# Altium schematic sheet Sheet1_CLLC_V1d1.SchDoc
size A3
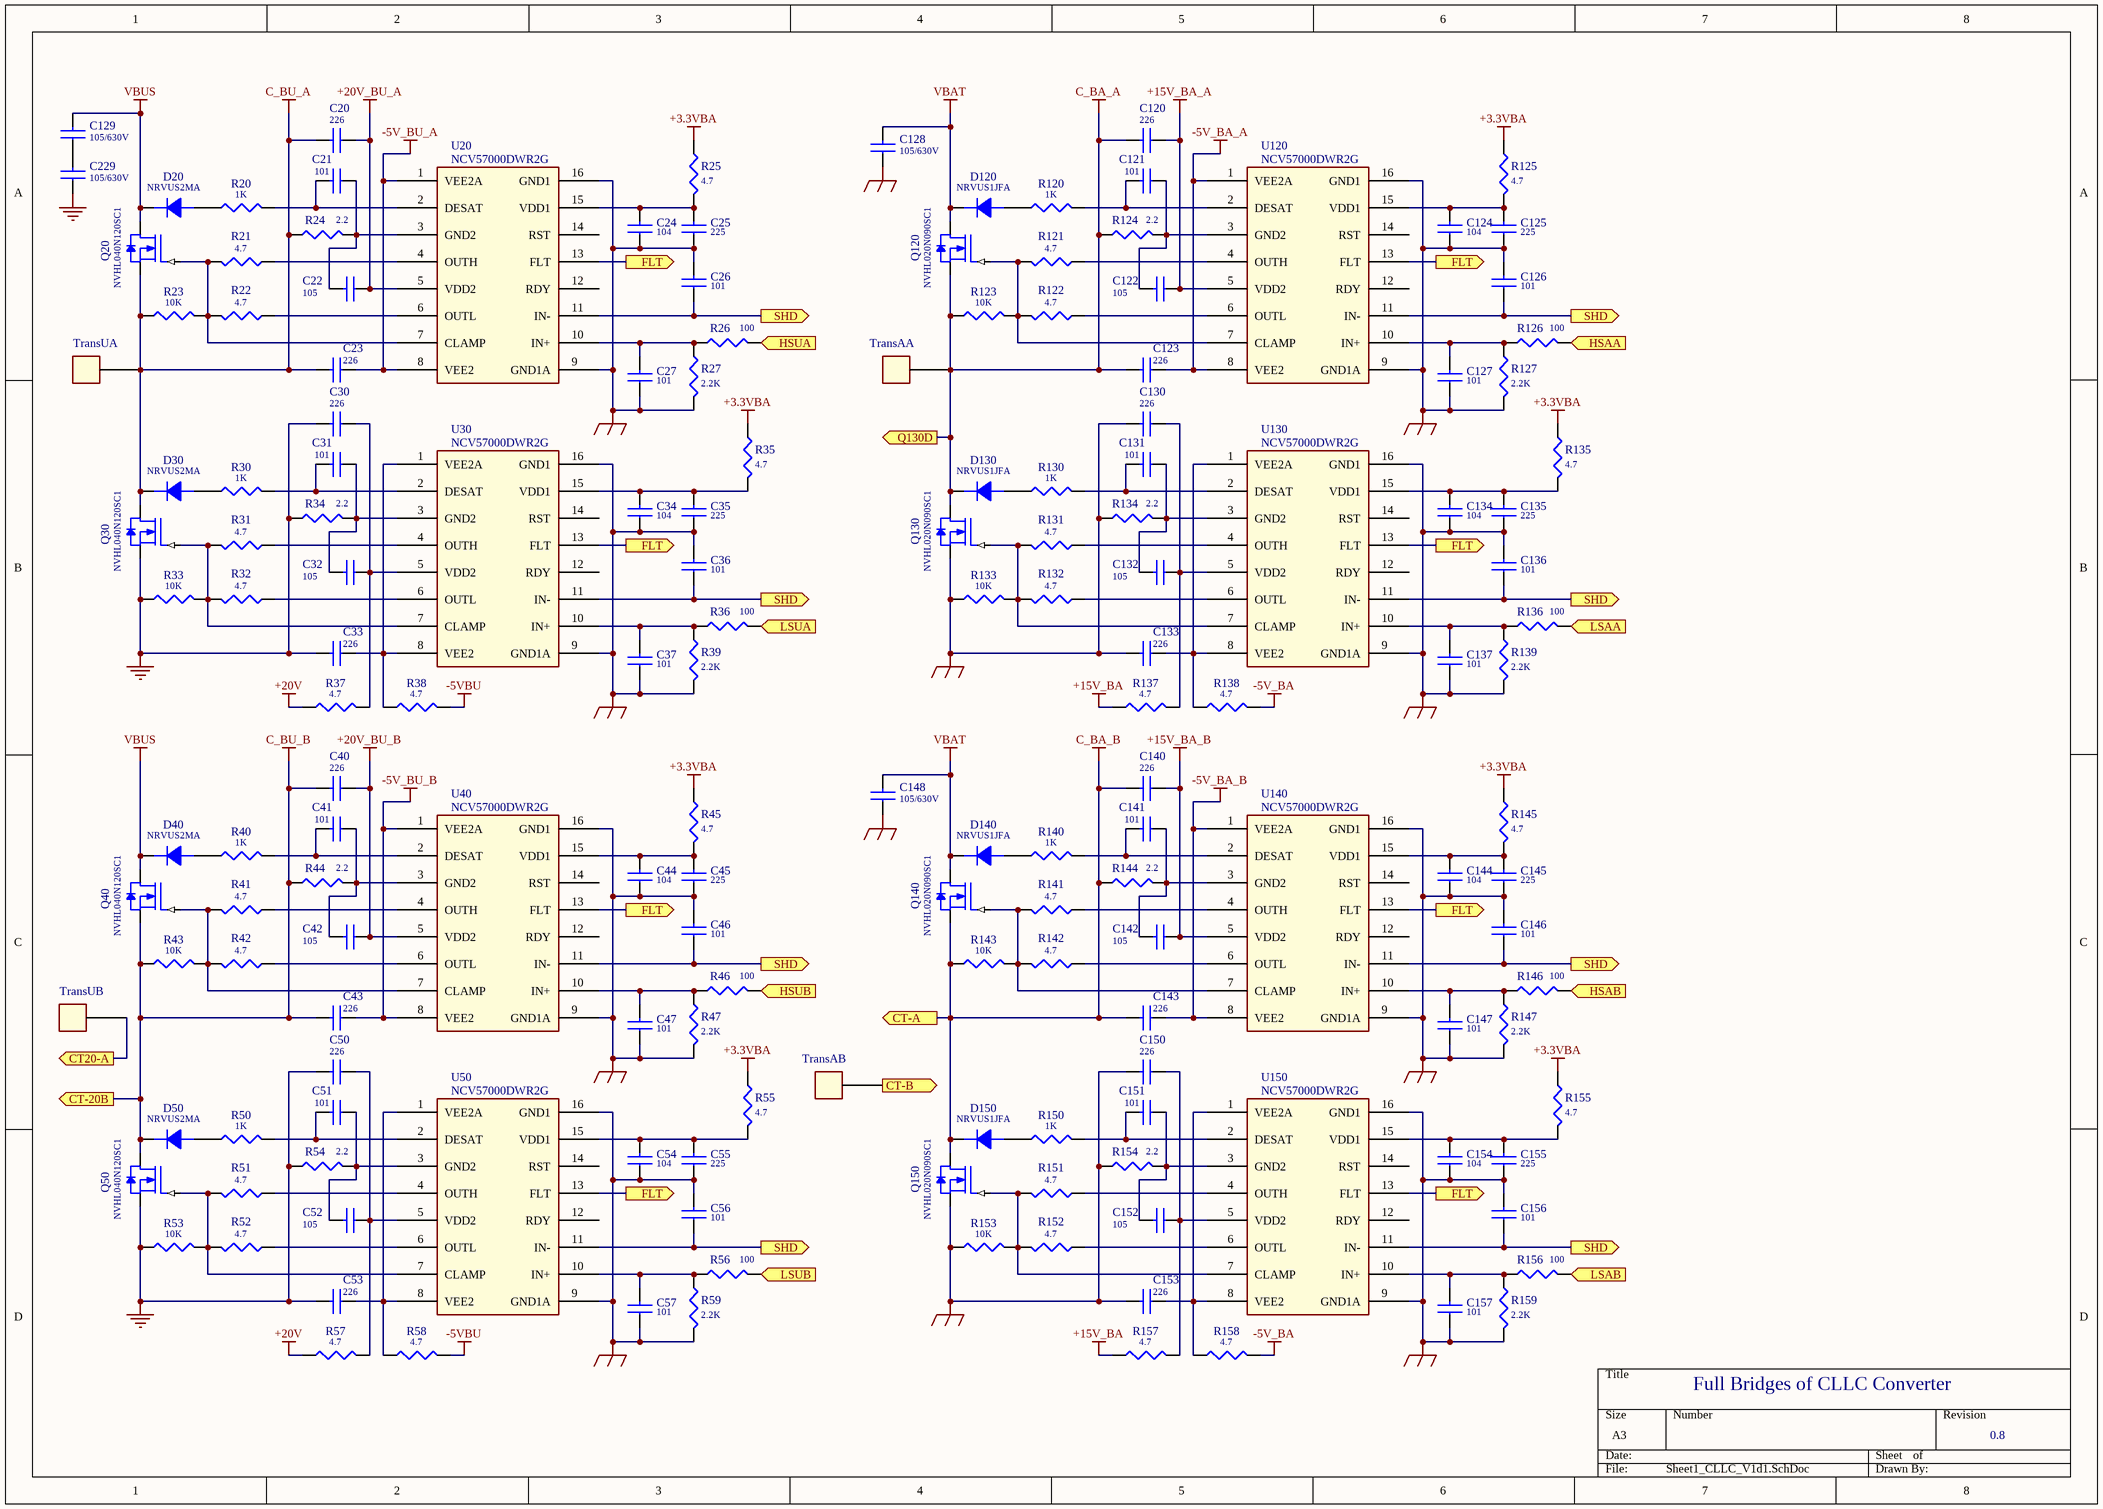
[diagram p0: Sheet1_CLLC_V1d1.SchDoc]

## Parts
C20  226  [SMT_1210]
C21  101  [SMT_0805_CM]
C22  105  [SMT_0805_CM]
C23  226  [SMT_1210]
C24  104  [SMT_0805_CM]
C25  225  [SMT_0805_CM]
C26  101  [SMT_0805_CM]
C27  101  [SMT_0805_CM]
C30  226  [SMT_1210]
C31  101  [SMT_0805_CM]
C32  105  [SMT_0805_CM]
C33  226  [SMT_1210]
C34  104  [SMT_0805_CM]
C35  225  [SMT_0805_CM]
C36  101  [SMT_0805_CM]
C37  101  [SMT_0805_CM]
C40  226  [SMT_1210]
C41  101  [SMT_0805_CM]
C42  105  [SMT_0805_CM]
C43  226  [SMT_1210]
C44  104  [SMT_0805_CM]
C45  225  [SMT_0805_CM]
C46  101  [SMT_0805_CM]
C47  101  [SMT_0805_CM]
C50  226  [SMT_1210]
C51  101  [SMT_0805_CM]
C52  105  [SMT_0805_CM]
C53  226  [SMT_1210]
C54  104  [SMT_0805_CM]
C55  225  [SMT_0805_CM]
C56  101  [SMT_0805_CM]
C57  101  [SMT_0805_CM]
C120  226  [SMT_1210]
C121  101  [SMT_0805_CM]
C122  105  [SMT_0805_CM]
C123  226  [SMT_1210]
C124  104  [SMT_0805_CM]
C125  225  [SMT_0805_CM]
C126  101  [SMT_0805_CM]
C127  101  [SMT_0805_CM]
C128  105/630V  [CAP2220]
C129  105/630V  [CAP2220]
C130  226  [SMT_1210]
C131  101  [SMT_0805_CM]
C132  105  [SMT_0805_CM]
C133  226  [SMT_1210]
C134  104  [SMT_0805_CM]
C135  225  [SMT_0805_CM]
C136  101  [SMT_0805_CM]
C137  101  [SMT_0805_CM]
C140  226  [SMT_1210]
C141  101  [SMT_0805_CM]
C142  105  [SMT_0805_CM]
C143  226  [SMT_1210]
C144  104  [SMT_0805_CM]
C145  225  [SMT_0805_CM]
C146  101  [SMT_0805_CM]
C147  101  [SMT_0805_CM]
C148  105/630V  [CAP2220]
C150  226  [SMT_1210]
C151  101  [SMT_0805_CM]
C152  105  [SMT_0805_CM]
C153  226  [SMT_1210]
C154  104  [SMT_0805_CM]
C155  225  [SMT_0805_CM]
C156  101  [SMT_0805_CM]
C157  101  [SMT_0805_CM]
C229  105/630V  [CAP2220]
D20  NRVUS2MA  [DO-214AC(SMA)]
D30  NRVUS2MA  [DO-214AC(SMA)]
D40  NRVUS2MA  [DO-214AC(SMA)]
D50  NRVUS2MA  [DO-214AC(SMA)]
D120  NRVUS1JFA  [SOD-123FL]
D130  NRVUS1JFA  [SOD-123FL]
D140  NRVUS1JFA  [SOD-123FL]
D150  NRVUS1JFA  [SOD-123FL]
Q20  NVHL040N120SC1  [TO247]
Q30  NVHL040N120SC1  [TO247]
Q40  NVHL040N120SC1  [TO247]
Q50  NVHL040N120SC1  [TO247]
Q120  NVHL020N090SC1  [TO247]
Q130  NVHL020N090SC1  [TO247]
Q140  NVHL020N090SC1  [TO247]
Q150  NVHL020N090SC1  [TO247]
R20  1K  [SMT_0805_RM]
R21  4.7  [SMT_1206_RM]
R22  4.7  [SMT_1206_RM]
R23  10K  [SMT_0805_RM]
R24  2.2  [SMT_0805_RM]
R25  4.7  [SMT_0805_RM]
R26  100  [SMT_0805_RM]
R27  2.2K  [SMT_0805_RM]
R30  1K  [SMT_0805_RM]
R31  4.7  [SMT_1206_RM]
R32  4.7  [SMT_1206_RM]
R33  10K  [SMT_0805_RM]
R34  2.2  [SMT_0805_RM]
R35  4.7  [SMT_0805_RM]
R36  100  [SMT_0805_RM]
R37  4.7  [SMT_0805_RM]
R38  4.7  [SMT_0805_RM]
R39  2.2K  [SMT_0805_RM]
R40  1K  [SMT_0805_RM]
R41  4.7  [SMT_1206_RM]
R42  4.7  [SMT_1206_RM]
R43  10K  [SMT_0805_RM]
R44  2.2  [SMT_0805_RM]
R45  4.7  [SMT_0805_RM]
R46  100  [SMT_0805_RM]
R47  2.2K  [SMT_0805_RM]
R50  1K  [SMT_0805_RM]
R51  4.7  [SMT_1206_RM]
R52  4.7  [SMT_1206_RM]
R53  10K  [SMT_0805_RM]
R54  2.2  [SMT_0805_RM]
R55  4.7  [SMT_0805_RM]
R56  100  [SMT_0805_RM]
R57  4.7  [SMT_0805_RM]
R58  4.7  [SMT_0805_RM]
R59  2.2K  [SMT_0805_RM]
R120  1K  [SMT_0805_RM]
R121  4.7  [SMT_1206_RM]
R122  4.7  [SMT_1206_RM]
R123  10K  [SMT_0805_RM]
R124  2.2  [SMT_0805_RM]
R125  4.7  [SMT_0805_RM]
R126  100  [SMT_0805_RM]
R127  2.2K  [SMT_0805_RM]
R130  1K  [SMT_0805_RM]
R131  4.7  [SMT_1206_RM]
R132  4.7  [SMT_1206_RM]
R133  10K  [SMT_0805_RM]
R134  2.2  [SMT_0805_RM]
R135  4.7  [SMT_0805_RM]
R136  100  [SMT_0805_RM]
R137  4.7  [SMT_0805_RM]
R138  4.7  [SMT_0805_RM]
R139  2.2K  [SMT_0805_RM]
R140  1K  [SMT_0805_RM]
R141  4.7  [SMT_1206_RM]
R142  4.7  [SMT_1206_RM]
R143  10K  [SMT_0805_RM]
R144  2.2  [SMT_0805_RM]
R145  4.7  [SMT_0805_RM]
R146  100  [SMT_0805_RM]
R147  2.2K  [SMT_0805_RM]
R150  1K  [SMT_0805_RM]
R151  4.7  [SMT_1206_RM]
R152  4.7  [SMT_1206_RM]
R153  10K  [SMT_0805_RM]
R154  2.2  [SMT_0805_RM]
R155  4.7  [SMT_0805_RM]
R156  100  [SMT_0805_RM]
R157  4.7  [SMT_0805_RM]
R158  4.7  [SMT_0805_RM]
R159  2.2K  [SMT_0805_RM]
TransAA  (no value)  [TermL]
TransAB  (no value)  [TermL]
TransUA  (no value)  [TermL]
TransUB  (no value)  [TermL]
U20  NCV57000DWR2G  [SOP16W]
U30  NCV57000DWR2G  [SOP16W]
U40  NCV57000DWR2G  [SOP16W]
U50  NCV57000DWR2G  [SOP16W]
U120  NCV57000DWR2G  [SOP16W]
U130  NCV57000DWR2G  [SOP16W]
U140  NCV57000DWR2G  [SOP16W]
U150  NCV57000DWR2G  [SOP16W]

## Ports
CT20-A (out), CT-20B (out), CT-A (out), CT-B (out), FLT (out), HSAA (out), HSAB (out), HSUA (out), HSUB (out), LSAA (out), LSAB (out), LSUA (out), LSUB (out), Q130D (out), SHD (out)

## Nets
+3.3VBA: R25.1 R35.1 R45.1 R55.1 R125.1 R135.1 R145.1 R155.1
+15V_BA: R137.1 R157.1
+15V_BA_A: C120.1 C122.1 U120.5(VDD2)
+15V_BA_B: C140.1 C142.1 U140.5(VDD2)
+20V: R37.1 R57.1
+20V_BU_A: C20.1 C22.1 U20.5(VDD2)
+20V_BU_B: C40.1 C42.1 U40.5(VDD2)
-5V_BA: R138.2 R158.2
-5V_BA_A: C123.1 U120.1(VEE2A) U120.8(VEE2)
-5V_BA_B: C143.1 U140.1(VEE2A) U140.8(VEE2)
-5V_BU_A: C23.1 U20.1(VEE2A) U20.8(VEE2)
-5V_BU_B: C43.1 U40.1(VEE2A) U40.8(VEE2)
-5VBU: R38.2 R58.2
C_BA_A: C120.2 C123.2 D130.2(K) Q120.3(SOURCE) Q130.2(DRAIN) R123.1 R124.1 TransAA.1 ; port Q130D
C_BA_B: C140.2 C143.2 D150.2(K) Q140.3(SOURCE) Q150.2(DRAIN) R143.1 R144.1 ; port CT-A
C_BU_A: C20.2 C23.2 D30.2(K) Q20.3(SOURCE) Q30.2(DRAIN) R23.1 R24.1 TransUA.1
C_BU_B: C40.2 C43.2 D50.2(K) Q40.3(SOURCE) Q50.2(DRAIN) R43.1 R44.1 ; port CT-20B
GND: C24.1 C25.1 C26.2 C27.1 C34.1 C35.1 C36.2 C37.1 C44.1 C45.1 C46.2 C47.1 C54.1 C55.1 C56.2 C57.1 C124.1 C125.1 C126.2 C127.1 C128.1 C130.2 C133.2 C134.1 C135.1 C136.2 C137.1 C144.1 C145.1 C146.2 C147.1 C148.1 C150.2 C153.2 C154.1 C155.1 C156.2 C157.1 Q130.3(SOURCE) Q150.3(SOURCE) R27.2 R39.2 R47.2 R59.2 R127.2 R133.1 R134.1 R139.2 R147.2 R153.1 R154.1 R159.2 U20.9(GND1A) U20.16(GND1) U30.9(GND1A) U30.16(GND1) U40.9(GND1A) U40.16(GND1) U50.9(GND1A) U50.16(GND1) U120.9(GND1A) U120.16(GND1) U130.9(GND1A) U130.16(GND1) U140.9(GND1A) U140.16(GND1) U150.9(GND1A) U150.16(GND1)
PGND: C30.2 C33.2 C50.2 C53.2 C229.1 Q30.3(SOURCE) Q50.3(SOURCE) R33.1 R34.1 R53.1 R54.1
VBAT: C128.2 C148.2 D120.2(K) D140.2(K) Q120.2(DRAIN) Q140.2(DRAIN)
VBUS: C129.2 D20.2(K) D40.2(K) Q20.2(DRAIN) Q40.2(DRAIN)
CT20-A: TransUB.1 ; port CT20-A
CT-B: TransAB.1 ; port CT-B
FLT: U20.13(FLT) U30.13(FLT) U40.13(FLT) U50.13(FLT) U120.13(FLT) U130.13(FLT) U140.13(FLT) U150.13(FLT) ; port FLT
HSAA: R126.2 ; port HSAA
HSAB: R146.2 ; port HSAB
HSUA: R26.2 ; port HSUA
HSUB: R46.2 ; port HSUB
LSAA: R136.2 ; port LSAA
LSAB: R156.2 ; port LSAB
LSUA: R36.2 ; port LSUA
LSUB: R56.2 ; port LSUB
SHD: C26.1 C36.1 C46.1 C56.1 C126.1 C136.1 C146.1 C156.1 U20.11(IN-) U30.11(IN-) U40.11(IN-) U50.11(IN-) U120.11(IN-) U130.11(IN-) U140.11(IN-) U150.11(IN-) ; port SHD
NetC21_1: C21.1 C22.2 R24.2 U20.3(GND2)
NetC21_2: C21.2 R20.2 U20.2(DESAT)
NetC24_2: C24.2 C25.2 R25.2 U20.15(VDD1)
NetC27_2: C27.2 R26.1 R27.1 U20.10(IN+)
NetC30_1: C30.1 C32.1 R37.2 U30.5(VDD2)
NetC31_1: C31.1 C32.2 R34.2 U30.3(GND2)
NetC31_2: C31.2 R30.2 U30.2(DESAT)
NetC33_1: C33.1 R38.1 U30.1(VEE2A) U30.8(VEE2)
NetC34_2: C34.2 C35.2 R35.2 U30.15(VDD1)
NetC37_2: C37.2 R36.1 R39.1 U30.10(IN+)
NetC41_1: C41.1 C42.2 R44.2 U40.3(GND2)
NetC41_2: C41.2 R40.2 U40.2(DESAT)
NetC44_2: C44.2 C45.2 R45.2 U40.15(VDD1)
NetC47_2: C47.2 R46.1 R47.1 U40.10(IN+)
NetC50_1: C50.1 C52.1 R57.2 U50.5(VDD2)
NetC51_1: C51.1 C52.2 R54.2 U50.3(GND2)
NetC51_2: C51.2 R50.2 U50.2(DESAT)
NetC53_1: C53.1 R58.1 U50.1(VEE2A) U50.8(VEE2)
NetC54_2: C54.2 C55.2 R55.2 U50.15(VDD1)
NetC57_2: C57.2 R56.1 R59.1 U50.10(IN+)
NetC121_1: C121.1 C122.2 R124.2 U120.3(GND2)
NetC121_2: C121.2 R120.2 U120.2(DESAT)
NetC124_2: C124.2 C125.2 R125.2 U120.15(VDD1)
NetC127_2: C127.2 R126.1 R127.1 U120.10(IN+)
NetC129_1: C129.1 C229.2
NetC130_1: C130.1 C132.1 R137.2 U130.5(VDD2)
NetC131_1: C131.1 C132.2 R134.2 U130.3(GND2)
NetC131_2: C131.2 R130.2 U130.2(DESAT)
NetC133_1: C133.1 R138.1 U130.1(VEE2A) U130.8(VEE2)
NetC134_2: C134.2 C135.2 R135.2 U130.15(VDD1)
NetC137_2: C137.2 R136.1 R139.1 U130.10(IN+)
NetC141_1: C141.1 C142.2 R144.2 U140.3(GND2)
NetC141_2: C141.2 R140.2 U140.2(DESAT)
NetC144_2: C144.2 C145.2 R145.2 U140.15(VDD1)
NetC147_2: C147.2 R146.1 R147.1 U140.10(IN+)
NetC150_1: C150.1 C152.1 R157.2 U150.5(VDD2)
NetC151_1: C151.1 C152.2 R154.2 U150.3(GND2)
NetC151_2: C151.2 R150.2 U150.2(DESAT)
NetC153_1: C153.1 R158.1 U150.1(VEE2A) U150.8(VEE2)
NetC154_2: C154.2 C155.2 R155.2 U150.15(VDD1)
NetC157_2: C157.2 R156.1 R159.1 U150.10(IN+)
NetD20_1: D20.1(A) R20.1
NetD30_1: D30.1(A) R30.1
NetD40_1: D40.1(A) R40.1
NetD50_1: D50.1(A) R50.1
NetD120_1: D120.1(A) R120.1
NetD130_1: D130.1(A) R130.1
NetD140_1: D140.1(A) R140.1
NetD150_1: D150.1(A) R150.1
NetQ20_1: Q20.1(GATE) R21.2 R22.2 R23.2 U20.7(CLAMP)
NetQ30_1: Q30.1(GATE) R31.2 R32.2 R33.2 U30.7(CLAMP)
NetQ40_1: Q40.1(GATE) R41.2 R42.2 R43.2 U40.7(CLAMP)
NetQ50_1: Q50.1(GATE) R51.2 R52.2 R53.2 U50.7(CLAMP)
NetQ120_1: Q120.1(GATE) R121.2 R122.2 R123.2 U120.7(CLAMP)
NetQ130_1: Q130.1(GATE) R131.2 R132.2 R133.2 U130.7(CLAMP)
NetQ140_1: Q140.1(GATE) R141.2 R142.2 R143.2 U140.7(CLAMP)
NetQ150_1: Q150.1(GATE) R151.2 R152.2 R153.2 U150.7(CLAMP)
NetR21_1: R21.1 U20.4(OUTH)
NetR22_1: R22.1 U20.6(OUTL)
NetR31_1: R31.1 U30.4(OUTH)
NetR32_1: R32.1 U30.6(OUTL)
NetR41_1: R41.1 U40.4(OUTH)
NetR42_1: R42.1 U40.6(OUTL)
NetR51_1: R51.1 U50.4(OUTH)
NetR52_1: R52.1 U50.6(OUTL)
NetR121_1: R121.1 U120.4(OUTH)
NetR122_1: R122.1 U120.6(OUTL)
NetR131_1: R131.1 U130.4(OUTH)
NetR132_1: R132.1 U130.6(OUTL)
NetR141_1: R141.1 U140.4(OUTH)
NetR142_1: R142.1 U140.6(OUTL)
NetR151_1: R151.1 U150.4(OUTH)
NetR152_1: R152.1 U150.6(OUTL)

Not connected (* = marked no-connect by the designer): U20 12(RDY) 14(RST); U30 12(RDY) 14(RST); U40 12(RDY) 14(RST); U50 12(RDY) 14(RST); U120 12(RDY) 14(RST); U130 12(RDY) 14(RST); U140 12(RDY) 14(RST); U150 12(RDY) 14(RST)

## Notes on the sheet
- Full Bridges of CLLC Converter
- 0.8

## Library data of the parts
C20 C23 C30 C33 C40 C43 C50 C53 C120 C123 C128-C130 C133 C140 C143 C148 C150 C153 C229 = CAP NP
C21 C31 C41 C51 C121 C131 C141 C151 = CAP_1206
C22 C24-C27 C32 C34-C37 C42 C44-C47 C52 C54-C57 C122 C124-C127 C132 C134-C137 C142 C144-C147 C152 C154-C157 = CAP_0805
D20 D30 D40 D50 D120 D130 D140 D150 = D_SMA(DO-214AC)
Q20 Q30 Q40 Q50 Q120 Q130 Q140 Q150 = SICMOS
R20 R23 R24 R26 R30 R33 R34 R36-R38 R40 R43 R44 R46 R50 R53 R54 R56-R58 R120 R123 R124 R126 R130 R133 R134 R136-R138 R140 R143 R144 R146 R150 R153 R154 R156-R158 = R_0805
R21 R22 R25 R27 R31 R32 R35 R39 R41 R42 R45 R47 R51 R52 R55 R59 R121 R122 R125 R127 R131 R132 R135 R139 R141 R142 R145 R147 R151 R152 R155 R159 = R
TransAA TransAB TransUA TransUB = P_1
U20 U30 U40 U50 U120 U130 U140 U150 = U_NCV57000_SO-16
